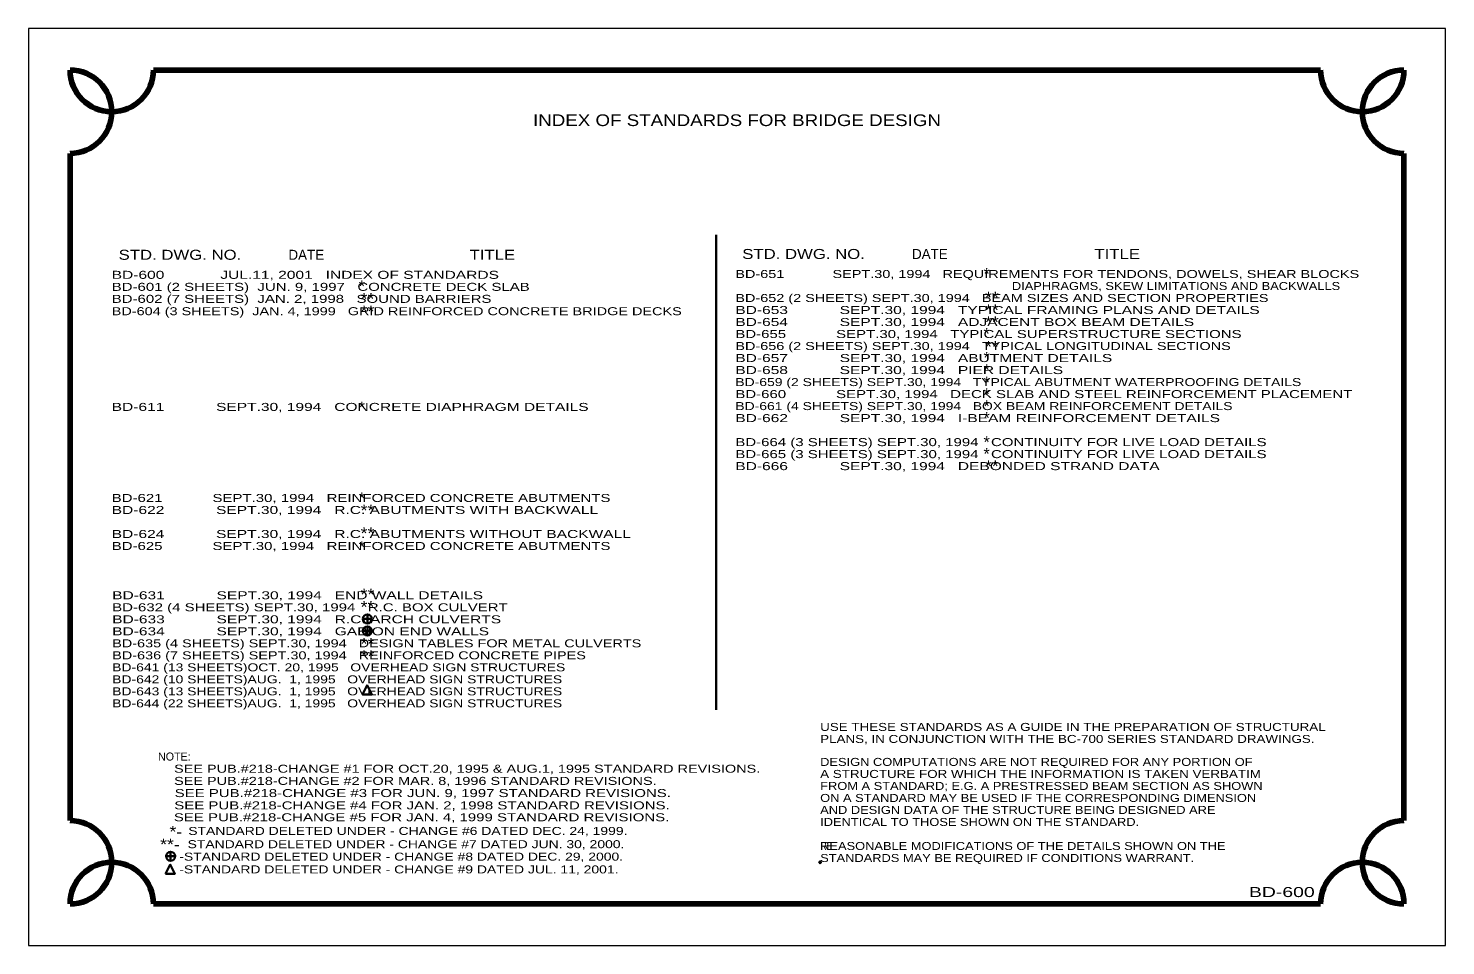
# Model space of a CAD drawing. Extents: x 763.8 to 797.8, y -170.3 to -127.3.
# Drawn here: x 763.76 to 797.76, y -170.27 to -148.27 of the extents above; entities that cross this region are included whole.
import ezdxf
from ezdxf.enums import TextEntityAlignment as Align

# ---------------------------------------------------------------- set-up
doc = ezdxf.new("R2010")
doc.units = 0
doc.header["$LTSCALE"] = 0.077
doc.header["$PDMODE"] = 32
doc.header["$PDSIZE"] = 0.0385
doc.layers.add('1', color=7, linetype='Continuous', lineweight=35)
doc.layers.add('3', color=7, linetype='Continuous', lineweight=35)
doc.layers.add('2', color=7, linetype='Continuous')

msp = doc.modelspace()

# ---------------------------------------------------------------- linework, layer by layer
at = {"layer": '1', "lineweight": 80}
for p, q in [((794.76075, -149.26542), (766.76075, -149.26542)), ((764.76075, -151.26542), (764.76075, -167.26542)), ((796.76075, -167.26542), (796.76075, -151.26542)), ((766.76075, -169.26542), (794.76075, -169.26542))]:
    msp.add_line(p, q, dxfattribs=at)
at = {"layer": '1'}
for p, q in [((771.78575, -162.42875), (772.00167, -162.42875)), ((771.89367, -162.32092), (771.89367, -162.53692)), ((771.78683, -162.7175), (772.00283, -162.7175)), ((771.89475, -162.82533), (771.89475, -162.60942)), ((767.06492, -168.12192), (767.28092, -168.12192)), ((767.17283, -168.22975), (767.17283, -168.01383))]:
    msp.add_line(p, q, dxfattribs=at)
at = {"layer": '1', "lineweight": 13}
msp.add_lwpolyline([(763.76075, -170.26542), (797.76075, -170.26542), (797.76075, -148.26542), (763.76075, -148.26542)], close=True, dxfattribs=at)
at = {"layer": '1'}
for points in [[(771.77583, -164.24042), (771.88667, -164.01883), (771.99742, -164.24042)], [(767.05392, -168.54242), (767.16475, -168.32083), (767.2755, -168.54242)]]:
    msp.add_lwpolyline(points, close=True, dxfattribs=at)
for centre in [(771.89364, -162.42881), (771.89478, -162.71743), (767.17285, -168.12183)]:
    msp.add_circle(centre, 0.10799, dxfattribs=at)
at = {"layer": '1', "lineweight": 80}
for centre, start, end in [((764.76073, -150.26542), 270, 90), ((765.76073, -149.26542), 180, 0), ((795.76073, -149.26542), 180, 0), ((796.76073, -150.26542), 90, 270), ((764.76073, -168.26542), 270, 90), ((796.76073, -168.26542), 90, 270), ((765.76073, -169.26542), 0, 180), ((795.76073, -169.26542), 0, 180)]:
    msp.add_arc(centre, 1, start, end, dxfattribs=at)
at = {"layer": '3'}
msp.add_line((780.26075, -164.61108), (780.26075, -153.22), dxfattribs=at)
msp.add_point((782.75483, -168.26542), dxfattribs=at)

# ---------------------------------------------------------------- texts
at = {"layer": '1'}
for s, height, width, p in [('*', 0.2765, 1.05, (786.74987, -154.289)), ('*', 0.2765, 1.05, (771.76258, -154.58633)), ('**', 0.2765, 1.15, (771.8965, -154.89092)), ('**', 0.2765, 1.15, (786.87483, -154.85758)), ('**', 0.2765, 1.15, (771.8965, -155.18908)), ('**', 0.2765, 1.15, (786.87483, -155.15975)), ('**', 0.2765, 1.15, (786.87483, -155.44892)), ('*', 0.2765, 1.05, (786.74987, -155.7285)), ('*', 0.2765, 1.05, (786.74987, -156.30183)), ('**', 0.2765, 1.15, (786.87483, -156.03758)), ('*', 0.2765, 1.05, (786.74987, -156.60033)), ('*', 0.2765, 1.05, (786.74987, -156.893)), ('*', 0.2765, 1.05, (786.74987, -157.17367)), ('*', 0.2765, 1.05, (771.76262, -157.49133)), ('*', 0.2765, 1.05, (786.74987, -157.46633)), ('*', 0.2765, 1.05, (786.74987, -157.747)), ('*', 0.2765, 1.05, (786.74987, -158.32633)), ('*', 0.2765, 1.05, (786.74987, -158.607)), ('**', 0.2765, 1.15, (786.87483, -158.90442)), ('*', 0.2765, 1.05, (771.76262, -159.67083)), ('**', 0.2765, 1.15, (771.8965, -159.96392)), ('**', 0.2765, 1.15, (771.8965, -160.51275)), ('*', 0.2765, 1.05, (771.76262, -160.84167)), ('**', 0.2765, 1.15, (771.8965, -161.98025)), ('**', 0.2765, 1.15, (771.8965, -162.27825)), ('**', 0.2765, 1.15, (771.8965, -163.16275)), ('**', 0.2765, 1.15, (771.8965, -163.46075)), ('*-', 0.2765, 1.15, (767.29975, -167.66858)), ('**-', 0.2765, 1.15, (767.15796, -167.97475)), ('BD-600', 0.24, 1.45, (793.83058, -169.1))]:
    msp.add_text(s, height=height, dxfattribs=dict(at, width=width)).set_placement(p, align=Align.CENTER)
at = {"layer": '1', "width": 1.3}
for s, p in [('STANDARD DELETED UNDER - CHANGE #6 DATED DEC. 24, 1999.', (767.5975, -167.6105)), ('STANDARD DELETED UNDER - CHANGE #7 DATED JUN. 30, 2000.', (767.58083, -167.928)), ('-STANDARD DELETED UNDER - CHANGE #8 DATED DEC. 29, 2000.', (767.38192, -168.22642)), ('-STANDARD DELETED UNDER - CHANGE #9 DATED JUL. 11, 2001.', (767.38183, -168.533))]:
    msp.add_text(s, height=0.192, dxfattribs=at).set_placement(p)
at = {"layer": '2'}
msp.add_text('NOTE:', height=0.192, dxfattribs=at).set_placement((766.87142, -165.82608))
for s, width, p in [('    SEE PUB.#218-CHANGE #1 FOR OCT.20, 1995 & AUG.1, 1995 STANDARD REVISIONS.', 1.35, (766.87142, -166.11808)), ('    SEE PUB.#218-CHANGE #2 FOR MAR. 8, 1996 STANDARD REVISIONS.', 1.35, (766.87142, -166.41008)), ('    SEE PUB.#218-CHANGE #3 FOR JUN. 9, 1997 STANDARD REVISIONS.   ', 1.4, (766.87142, -166.70208)), ('    SEE PUB.#218-CHANGE #4 FOR JAN. 2, 1998 STANDARD REVISIONS.   ', 1.4, (766.86192, -166.99717)), ('    SEE PUB.#218-CHANGE #5 FOR JAN. 4, 1999 STANDARD REVISIONS.   ', 1.4, (766.85242, -167.28267))]:
    msp.add_text(s, height=0.192, dxfattribs=dict(at, width=width)).set_placement(p)
at = {"layer": '3'}
for s, height, width, p in [('INDEX OF STANDARDS FOR BRIDGE DESIGN', 0.28, 1.2, (780.76071, -150.6085)), ('STD. DWG. NO.', 0.24, 1.25, (767.39767, -153.81658)), ('TITLE', 0.24, 1.25, (774.89104, -153.81658)), ('STD. DWG. NO.', 0.24, 1.25, (782.35767, -153.79658)), ('TITLE', 0.24, 1.25, (789.88196, -153.79658))]:
    msp.add_text(s, height=height, dxfattribs=dict(at, width=width)).set_placement(p, align=Align.CENTER)
for p in [(770.42796, -153.81658), (785.38796, -153.79658)]:
    msp.add_text('DATE', height=0.24, dxfattribs=at).set_placement(p, align=Align.CENTER)
for s, width, p in [('BD-601 (2 SHEETS)  JUN. 9, 1997   CONCRETE DECK SLAB', 1.4, (765.76075, -154.56083)), ('BD-600             JUL.11, 2001   INDEX OF STANDARDS', 1.45, (765.76075, -154.27283)), ('BD-651            SEPT.30, 1994   REQUIREMENTS FOR TENDONS, DOWELS, SHEAR BLOCKS', 1.35, (780.72075, -154.25283)), ('DIAPHRAGMS, SKEW LIMITATIONS AND BACKWALLS', 1.2, (787.35508, -154.54083)), ('BD-602 (7 SHEETS)  JAN. 2, 1998   SOUND BARRIERS', 1.4, (765.76075, -154.84883)), ('BD-652 (2 SHEETS) SEPT.30, 1994   BEAM SIZES AND SECTION PROPERTIES', 1.35, (780.72075, -154.82883)), ('BD-604 (3 SHEETS)  JAN. 4, 1999   GRID REINFORCED CONCRETE BRIDGE DECKS', 1.35, (765.76075, -155.14558)), ('BD-653            SEPT.30, 1994   TYPICAL FRAMING PLANS AND DETAILS', 1.45, (780.72075, -155.11683)), ('BD-654            SEPT.30, 1994   ADJACENT BOX BEAM DETAILS', 1.45, (780.72075, -155.40483)), ('BD-655            SEPT.30, 1994   TYPICAL SUPERSTRUCTURE SECTIONS', 1.4, (780.72075, -155.69283)), ('BD-656 (2 SHEETS) SEPT.30, 1994   TYPICAL LONGITUDINAL SECTIONS', 1.35, (780.72075, -155.98083)), ('BD-657            SEPT.30, 1994   ABUTMENT DETAILS', 1.45, (780.72075, -156.26883)), ('BD-658            SEPT.30, 1994   PIER DETAILS', 1.45, (780.72075, -156.55683)), ('BD-659 (2 SHEETS) SEPT.30, 1994   TYPICAL ABUTMENT WATERPROOFING DETAILS', 1.3, (780.72075, -156.84483)), ('BD-660            SEPT.30, 1994   DECK SLAB AND STEEL REINFORCEMENT PLACEMENT', 1.4, (780.72075, -157.13283)), ('BD-611            SEPT.30, 1994   CONCRETE DIAPHRAGM DETAILS', 1.45, (765.76075, -157.44083)), ('BD-661 (4 SHEETS) SEPT.30, 1994   BOX BEAM REINFORCEMENT DETAILS', 1.3, (780.72075, -157.42083)), ('BD-662            SEPT.30, 1994   I-BEAM REINFORCEMENT DETAILS', 1.45, (780.72075, -157.70883)), ('BD-664 (3 SHEETS) SEPT.30, 1994   CONTINUITY FOR LIVE LOAD DETAILS', 1.4, (780.72075, -158.28483)), ('BD-665 (3 SHEETS) SEPT.30, 1994   CONTINUITY FOR LIVE LOAD DETAILS', 1.4, (780.72075, -158.57283)), ('BD-666            SEPT.30, 1994   DEBONDED STRAND DATA', 1.45, (780.72075, -158.86083)), ('BD-621            SEPT.30, 1994   REINFORCED CONCRETE ABUTMENTS', 1.4, (765.76075, -159.6245)), ('BD-622            SEPT.30, 1994   R.C. ABUTMENTS WITH BACKWALL', 1.45, (765.76075, -159.9125)), ('BD-624            SEPT.30, 1994   R.C. ABUTMENTS WITHOUT BACKWALL', 1.45, (765.76075, -160.4885)), ('BD-625            SEPT.30, 1994   REINFORCED CONCRETE ABUTMENTS', 1.4, (765.76075, -160.7765)), ('BD-631            SEPT.30, 1994   END WALL DETAILS', 1.45, (765.77158, -161.9585)), ('BD-632 (4 SHEETS) SEPT.30, 1994   R.C. BOX CULVERT', 1.4, (765.77158, -162.2465)), ('BD-633            SEPT.30, 1994   R.C. ARCH CULVERTS', 1.45, (765.77158, -162.5345)), ('BD-634            SEPT.30, 1994   GABION END WALLS', 1.45, (765.77158, -162.8225)), ('BD-635 (4 SHEETS) SEPT.30, 1994   DESIGN TABLES FOR METAL CULVERTS', 1.35, (765.77158, -163.1105)), ('BD-636 (7 SHEETS) SEPT.30, 1994   REINFORCED CONCRETE PIPES', 1.35, (765.77158, -163.3985)), ('BD-641 (13 SHEETS)OCT. 20, 1995   OVERHEAD SIGN STRUCTURES', 1.3, (765.77158, -163.6865)), ('BD-642 (10 SHEETS)AUG.  1, 1995   OVERHEAD SIGN STRUCTURES', 1.3, (765.77158, -163.9745)), ('BD-643 (13 SHEETS)AUG.  1, 1995   OVERHEAD SIGN STRUCTURES', 1.3, (765.77158, -164.2625)), ('BD-644 (22 SHEETS)AUG.  1, 1995   OVERHEAD SIGN STRUCTURES', 1.3, (765.77158, -164.5505)), ('USE THESE STANDARDS AS A GUIDE IN THE PREPARATION OF STRUCTURAL', 1.25, (782.75583, -165.116)), ('PLANS, IN CONJUNCTION WITH THE BC-700 SERIES STANDARD DRAWINGS.', 1.25, (782.75583, -165.404)), ('DESIGN COMPUTATIONS ARE NOT REQUIRED FOR ANY PORTION OF', 1.2, (782.75583, -165.95508)), ('A STRUCTURE FOR WHICH THE INFORMATION IS TAKEN VERBATIM', 1.25, (782.75583, -166.24308)), ('FROM A STANDARD; E.G. A PRESTRESSED BEAM SECTION AS SHOWN', 1.2, (782.75583, -166.53108)), ('AND DESIGN DATA OF THE STRUCTURE BEING DESIGNED ARE', 1.2, (782.75583, -167.10708)), ('ON A STANDARD MAY BE U', 1.2, (782.75583, -166.81908)), ('ON A STANDARD MAY BE USED IF THE CORRESPONDING DIMENSION', 1.2, (782.75583, -166.81908)), ('IDENTICAL TO THOSE SHOWN ON THE STANDARD.', 1.2, (782.75583, -167.39508)), ('RE', 0.85, (782.75583, -167.97108)), ('REASONABLE MODIFICATIONS OF THE DETAILS SHOWN ON THE', 1.2, (782.75583, -167.97108)), ('STANDARDS MAY BE REQUIRED IF CONDITIONS WARRANT.', 1.2, (782.75583, -168.25908))]:
    msp.add_text(s, height=0.192, dxfattribs=dict(at, width=width)).set_placement(p)

doc.saveas('drawing.dxf')
